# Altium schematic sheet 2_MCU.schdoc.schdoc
size 309 x 223 mm; Symbol: Artery_A4; Device: Artery_A4; @Page Count: 4; @Create Date: 2024-01-02; @Page Name: MCU; @Project Name: AT-START-L021; @Update Date: 2024-02-21; @Schematic Name: AT-START-L021_V1.0; @Page No: 2; Company: Artery Technology; Drawed: SD; Version: 1.0; Page Size: A4
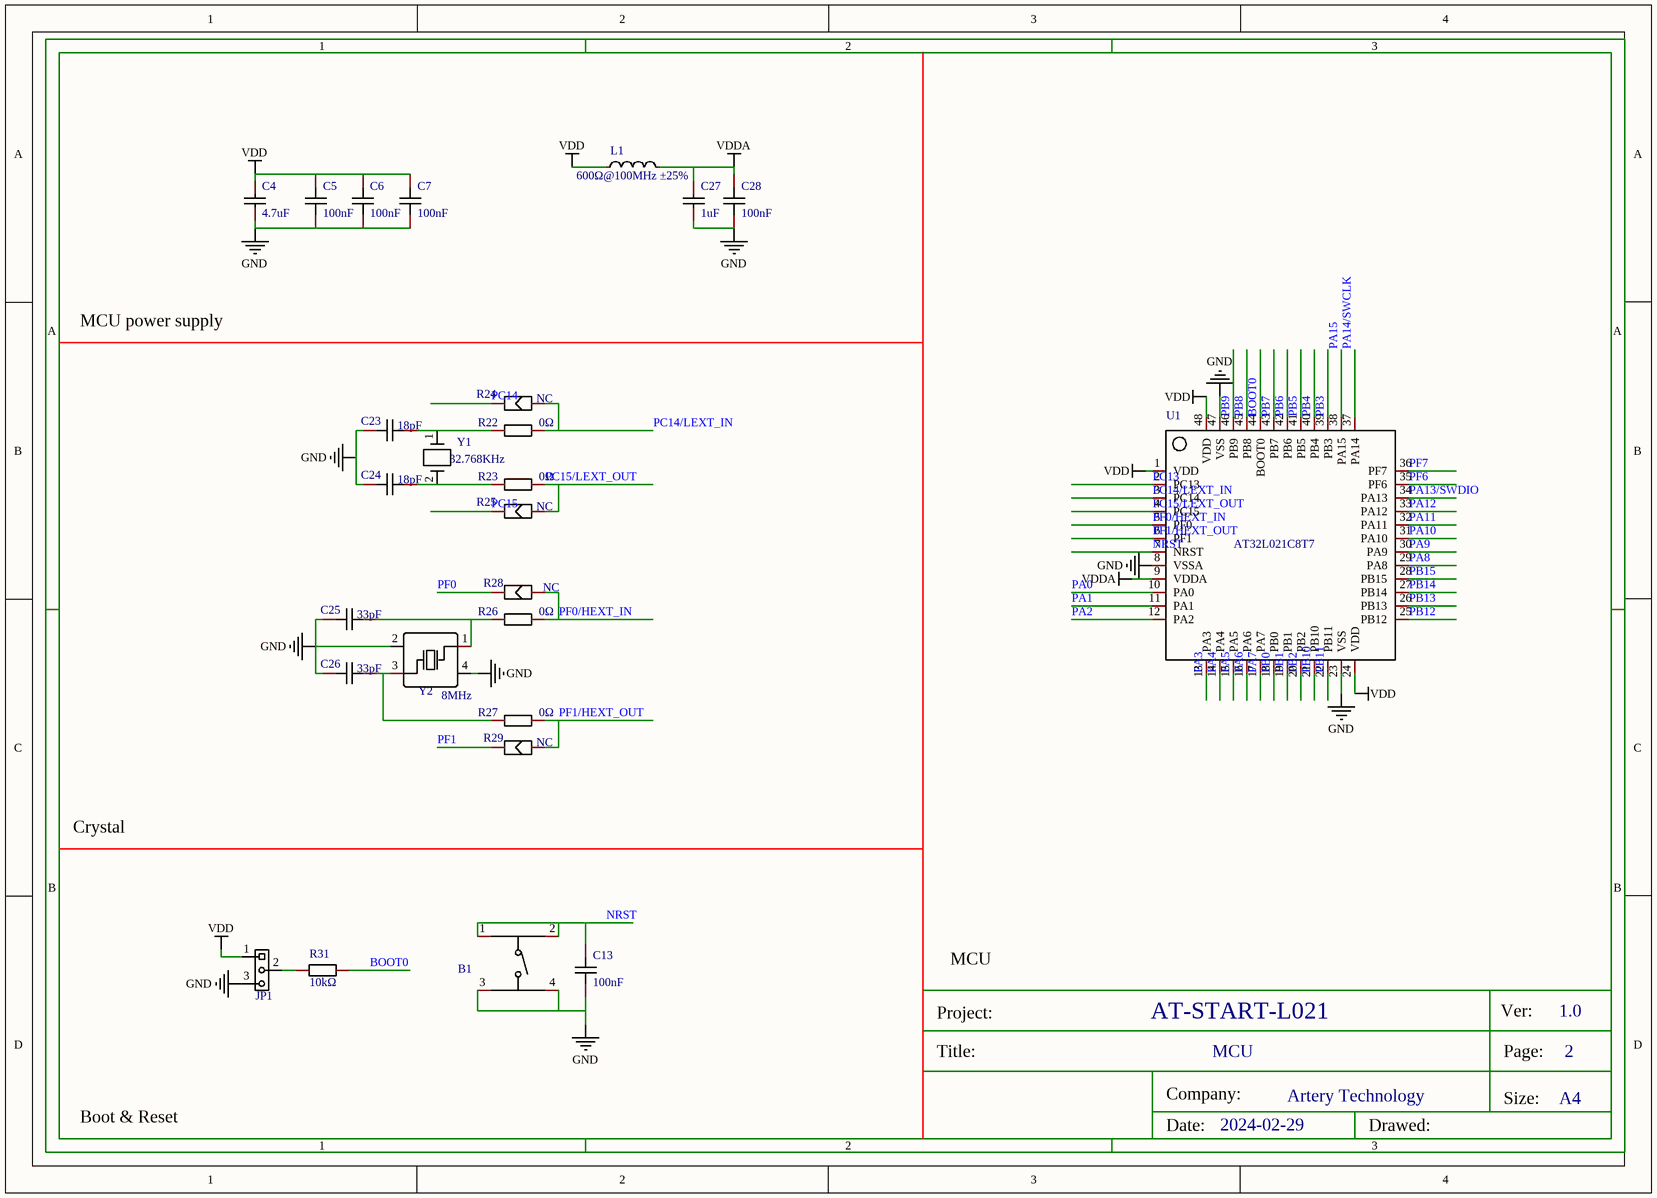
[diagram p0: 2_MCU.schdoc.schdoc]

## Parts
B1  K2-1102SP-C4SC-04  [BUTTON_SMT_6*6*5]  (value not drawn)
C4  value 4.7uF  [C0603]  (hidden comment: CL10A475KO8NNNC)
C5  value 100nF  [C0603]  (hidden comment: CC0603KRX7R9BB104)
C6  value 100nF  [C0603]  (hidden comment: CC0603KRX7R9BB104)
C7  value 100nF  [C0603]  (hidden comment: CC0603KRX7R9BB104)
C13  value 100nF  [C0603]  (hidden comment: CC0603KRX7R9BB104)
C23  18pF  [C0603]
C24  18pF  [C0603]
C25  33pF  [C0603]
C26  33pF  [C0603]
C27  value 1uF  [C0603]  (hidden comment: CL10A105KB8NNNC)
C28  value 100nF  [C0603]  (hidden comment: CC0603KRX7R9BB104)
JP1  Header 1x3  [HEADER 1X3]  (value not drawn)
L1  600Ω@100MHz ±25%  [L0603]
R22  value 0Ω  [R0603]  (hidden comment: 0603WAF0000T5E)
R23  value 0Ω  [R0603]  (hidden comment: 0603WAF0000T5E)
R24  NC  [SB-PAD]
R25  NC  [SB-PAD]
R26  value 0Ω  [R0603]  (hidden comment: 0603WAF0000T5E)
R27  value 0Ω  [R0603]  (hidden comment: 0603WAF0000T5E)
R28  NC  [SB-PAD]
R29  NC  [SB-PAD]
R31  value 10kΩ  [R0603]  (hidden comment: 0603WAF1002T5E)
U1  AT32L021C8T7  [LQFP-48_L7.0-W7.0-P0.50-LS9.0-BL]
Y1  32.768KHz  [XTAL_SOP - FC-12M]
Y2  8MHz  [OSC-SMD_4P-L5.0-W3.2-BL]

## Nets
GND: B1.3 B1.4 C4.1 C5.1 C6.1 C7.1 C13.1 C23.1 C24.1 C25.1 C26.1 C27.1 C28.1 JP1.3 U1.8(VSSA) U1.23(VSS) U1.47(VSS) Y2.2(GND) Y2.4(GND)
VDD: C4.2 C5.2 C6.2 C7.2 JP1.1 L1.1 U1.1(VDD) U1.24(VDD) U1.48(VDD)
VDDA: C27.2 C28.2 L1.2 U1.9(VDDA)
BOOT0: R31.2 U1.44(BOOT0)
NRST: B1.1 B1.2 C13.2 U1.7(NRST)
PA0: U1.10(PA0)
PA1: U1.11(PA1)
PA2: U1.12(PA2)
PA3: U1.13(PA3)
PA4: U1.14(PA4)
PA5: U1.15(PA5)
PA6: U1.16(PA6)
PA7: U1.17(PA7)
PA8: U1.29(PA8)
PA9: U1.30(PA9)
PA10: U1.31(PA10)
PA11: U1.32(PA11)
PA12: U1.33(PA12)
PA13/SWDIO: U1.34(PA13)
PA14/SWCLK: U1.37(PA14)
PA15: U1.38(PA15)
PB0: U1.18(PB0)
PB1: U1.19(PB1)
PB2: U1.20(PB2)
PB3: U1.39(PB3)
PB4: U1.40(PB4)
PB5: U1.41(PB5)
PB6: U1.42(PB6)
PB7: U1.43(PB7)
PB8: U1.45(PB8)
PB9: U1.46(PB9)
PB10: U1.21(PB10)
PB11: U1.22(PB11)
PB12: U1.25(PB12)
PB13: U1.26(PB13)
PB14: U1.27(PB14)
PB15: U1.28(PB15)
PC13: U1.2(PC13)
PC14: R24.2
PC14/LEXT_IN: R22.2 R24.1 U1.3(PC14)
PC15: R25.2
PC15/LEXT_OUT: R23.2 R25.1 U1.4(PC15)
PF0: R28.2
PF0/HEXT_IN: R26.2 R28.1 U1.5(PF0)
PF1: R29.2
PF1/HEXT_OUT: R27.2 R29.1 U1.6(PF1)
PF6: U1.35(PF6)
PF7: U1.36(PF7)
NetC23_2: C23.2 R22.1 Y1.1
NetC24_2: C24.2 R23.1 Y1.2
NetC25_2: C25.2 R26.1 Y2.1(OSC1)
NetC26_2: C26.2 R27.1 Y2.3(OSC2)
NetJP1_2: JP1.2 R31.1

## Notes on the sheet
- MCU power supply
- Crystal
- MCU
- Boot & Reset
- 2024-02-29

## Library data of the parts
B1 = K2-1102SP-C4SC-04: Manufacturer: 韩国韩荣; Add into BOM: yes; Contact Current: 50mA; Voltage Rating (DC): 12V; Insulation Resistance: 100MΩ; Circuit: 单刀单掷; Actuator Style: 圆形按钮; Operating Force: 250gf@±30gf; Mechanical Life: 100000; Switch Length: 6mm; Switch Height: 5mm; Description: 触点电流:50mA;额定电压(DC):12V;绝缘电阻:100MΩ;电路结构:单刀单掷;安装方式:立贴;按钮形状:圆形按钮;带灯:-;作用力:250gf@±30gf;机械寿命:100000;工作温度:-25℃~+85℃;开关长度:6mm;开关宽度:6mm;开关高度:5mm;
C4 = CL10A475KO8NNNC: Manufacturer: SAMSUNG(三星); Add into BOM: yes; Tolerance: ±10%; Voltage Rated: 16V; Temperature Coefficient: X5R; Description: 容值:4.7uF;精度:±10%;额定电压:16V;温度系数:X5R;
C5-C7 C13 C28 = CC0603KRX7R9BB104: Manufacturer: YAGEO(国巨); Add into BOM: yes; Tolerance: ±10%; Voltage Rated: 50V; Temperature Coefficient: X7R; Description: 容值:100nF;精度:±10%;额定电压:50V;温度系数:X7R;
C23 C24 = CL10C180JB8NNNC: Manufacturer: SAMSUNG(三星); Symbol: 10pF; Add into BOM: yes; Tolerance: ±5%; Voltage Rated: 50V; Temperature Coefficient: C0G; Description: 容值:18pF;精度:±5%;额定电压:50V;材质(温度系数):C0G;
C25 C26 = CL10C330JB8NNNC: Manufacturer: SAMSUNG(三星); Symbol: 22pF; Add into BOM: yes; Tolerance: ±5%; Voltage Rated: 50V; Temperature Coefficient: C0G; Description: 容值:33pF;精度:±5%;额定电压:50V;材质(温度系数):C0G;
C27 = CL10A105KB8NNNC: Manufacturer: SAMSUNG(三星); Add into BOM: yes; Tolerance: ±10%; Voltage Rated: 50V; Temperature Coefficient: X5R; Description: 容值:1uF;精度:±10%;额定电压:50V;温度系数:X5R;
JP1 = Header 1x3: Convert to PCB: yes
L1 = UPZ1608E601-1R0TF: Manufacturer: Sunlord(顺络); Add into BOM: yes; DC Resistance: 150mΩ; Current Rating: 1A; Circuits: 1; Description: 标称阻抗@测试频率:600Ω@100MHz;误差:±25%;直流电阻(RDC):150mΩ;额定电流:1A;电路数:1;
R22 R23 R26 R27 = 0603WAF0000T5E: 电阻类型:厚膜电阻;阻值:0Ω;精度:±1%;功率:1/10W;温度系数:-;最大工作电压:75V;工作温度范围:-55~+155;; Manufacturer: UNI-ROYAL(厚声); Add into BOM: yes; Tolerance: ±1%; Power(Watts): 1/10W; Overload Voltage (Max): 75V
R24 R28 R29 = NC_SB-PAD: Convert to PCB: yes
R25 = NC: Convert to PCB: yes
R31 = 0603WAF1002T5E: 电阻类型:厚膜电阻;阻值:10kΩ;精度:±1%;功率:1/10W;温度系数:±100ppm/;最大工作电压:75V;工作温度范围:-55~+155;; Manufacturer: UNI-ROYAL(厚声); Add into BOM: yes; Tolerance: ±1%; Power(Watts): 1/10W; Overload Voltage (Max): 75V
U1 = AT32L021C8T7: Manufacturer: ARTERY（雅特力）; Add into BOM: yes
Y1 = 32.768KHz: Convert to PCB: yes
Y2 = 8MHz_OSC-SMD_4P-L5.0-W3.2-BL: Manufacturer: YXC; Manufacturer Part: X50328MSD4SC; Paste Type: recommend; Convert to PCB: yes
